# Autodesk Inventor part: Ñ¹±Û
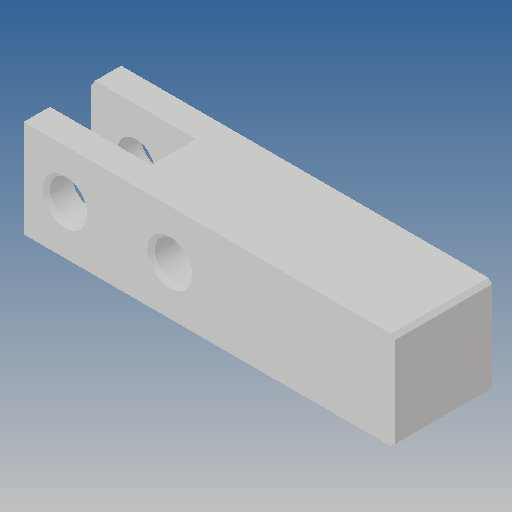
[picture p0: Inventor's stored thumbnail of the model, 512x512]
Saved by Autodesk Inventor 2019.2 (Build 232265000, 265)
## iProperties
Created: 2013-07
Part Number: Ñ¹±Û
Material: Ogólny
Document SubType Name: Modeling
Designer: CADENGINEERING4
Density: 1 g/cm^3
Appearance: Domyślna
Author: CADENGINEERING4
Revision Number: ÈÎºÎ
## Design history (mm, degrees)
feature "µ¹½Ç2"
node "Bryła1"
